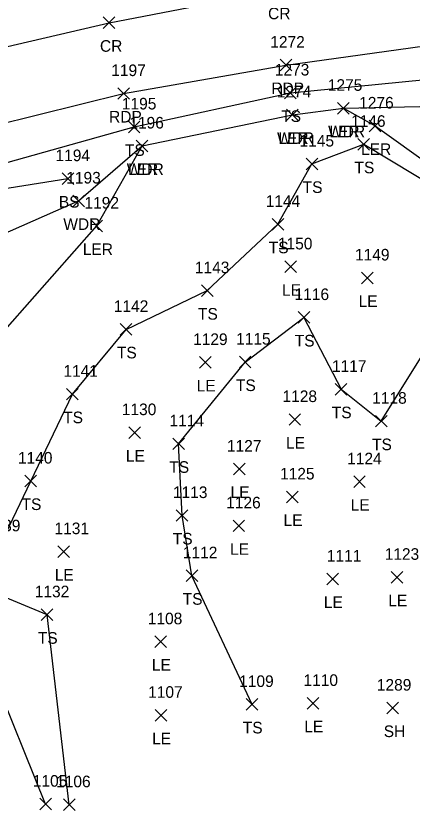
# Model space of a CAD drawing. Extents: x 1586965 to 1590952, y 716317 to 720029.
# Drawn here: x 1587642.6 to 1587710.9, y 719699 to 719836.9 of the extents above; entities that cross this region are included whole.
import ezdxf

# ---------------------------------------------------------------- set-up
doc = ezdxf.new("R2010")
doc.units = 0
for name, color, linetype in [('L_A', 7, 'Continuous'), ('L_I', 7, 'Continuous'), ('L_TIC', 7, 'Continuous'), ('LARO', 7, 'Continuous'), ('LAWA', 7, 'Continuous'), ('LELB', 7, 'Continuous'), ('P_A', 7, 'Continuous'), ('P_I', 7, 'Continuous'), ('P_TIC', 7, 'Continuous'), ('PET', 7, 'Continuous'), ('PRC', 7, 'Continuous')]:
    doc.layers.add(name, color=color, linetype=linetype)

msp = doc.modelspace()

# ---------------------------------------------------------------- linework, layer by layer
at = {"layer": 'L_TIC'}
for points in [[(1587688.98, 719822.61), (1587690.98, 719824.61)], [(1587690.98, 719822.61), (1587688.98, 719824.61)], [(1587689.31, 719818.83), (1587691.31, 719820.83)], [(1587691.31, 719818.83), (1587689.31, 719820.83)], [(1587689.31, 719818.83), (1587691.31, 719820.83)], [(1587691.31, 719818.83), (1587689.31, 719820.83)], [(1587698.11, 719819.97), (1587700.11, 719821.97)], [(1587700.11, 719819.97), (1587698.11, 719821.97)], [(1587698.11, 719819.97), (1587700.11, 719821.97)], [(1587700.11, 719819.97), (1587698.11, 719821.97)], [(1587662.03, 719816.76), (1587664.03, 719818.76)], [(1587664.03, 719816.76), (1587662.03, 719818.76)], [(1587703.58, 719816.92), (1587705.58, 719818.92)], [(1587705.58, 719816.92), (1587703.58, 719818.92)], [(1587663.38, 719813.47), (1587665.38, 719815.47)], [(1587665.38, 719813.47), (1587663.38, 719815.47)], [(1587663.38, 719813.47), (1587665.38, 719815.47)], [(1587665.38, 719813.47), (1587663.38, 719815.47)], [(1587701.61, 719813.76), (1587703.61, 719815.76)], [(1587703.61, 719813.76), (1587701.61, 719815.76)], [(1587692.68, 719810.37), (1587694.68, 719812.37)], [(1587694.68, 719810.37), (1587692.68, 719812.37)], [(1587650.6, 719807.85), (1587652.6, 719809.85)], [(1587652.6, 719807.85), (1587650.6, 719809.85)], [(1587652.44, 719804), (1587654.44, 719806)], [(1587654.44, 719804), (1587652.44, 719806)], [(1587655.59, 719799.68), (1587657.59, 719801.68)], [(1587657.59, 719799.68), (1587655.59, 719801.68)], [(1587686.83, 719799.98), (1587688.83, 719801.98)], [(1587688.83, 719799.98), (1587686.83, 719801.98)], [(1587689.03, 719792.65), (1587691.03, 719794.65)], [(1587691.03, 719792.65), (1587689.03, 719794.65)], [(1587702.24, 719790.74), (1587704.24, 719792.74)], [(1587704.24, 719790.74), (1587702.24, 719792.74)], [(1587674.63, 719788.54), (1587676.63, 719790.54)], [(1587676.63, 719788.54), (1587674.63, 719790.54)], [(1587691.31, 719783.92), (1587693.31, 719785.92)], [(1587693.31, 719783.92), (1587691.31, 719785.92)], [(1587660.64, 719781.87), (1587662.64, 719783.87)], [(1587662.64, 719781.87), (1587660.64, 719783.87)], [(1587674.32, 719776.17), (1587676.32, 719778.17)], [(1587676.32, 719776.17), (1587674.32, 719778.17)], [(1587681.17, 719776.24), (1587683.17, 719778.24)], [(1587683.17, 719776.24), (1587681.17, 719778.24)], [(1587651.38, 719770.7), (1587653.38, 719772.7)], [(1587653.38, 719770.7), (1587651.38, 719772.7)], [(1587697.7, 719771.55), (1587699.7, 719773.55)], [(1587699.7, 719771.55), (1587697.7, 719773.55)], [(1587689.74, 719766.34), (1587691.74, 719768.34)], [(1587691.74, 719766.34), (1587689.74, 719768.34)], [(1587704.64, 719766.05), (1587706.64, 719768.05)], [(1587706.64, 719766.05), (1587704.64, 719768.05)], [(1587662.11, 719764.09), (1587664.11, 719766.09)], [(1587664.11, 719764.09), (1587662.11, 719766.09)], [(1587669.68, 719762.15), (1587671.68, 719764.15)], [(1587671.68, 719762.15), (1587669.68, 719764.15)], [(1587680.16, 719757.8), (1587682.16, 719759.8)], [(1587682.16, 719757.8), (1587680.16, 719759.8)], [(1587644.2, 719755.74), (1587646.2, 719757.74)], [(1587646.2, 719755.74), (1587644.2, 719757.74)], [(1587700.88, 719755.61), (1587702.88, 719757.61)], [(1587702.88, 719755.61), (1587700.88, 719757.61)], [(1587689.3, 719753), (1587691.3, 719755)], [(1587691.3, 719753), (1587689.3, 719755)], [(1587670.28, 719749.8), (1587672.28, 719751.8)], [(1587672.28, 719749.8), (1587670.28, 719751.8)], [(1587680.08, 719748.02), (1587682.08, 719750.02)], [(1587682.08, 719748.02), (1587680.08, 719750.02)], [(1587649.85, 719743.58), (1587651.85, 719745.58)], [(1587651.85, 719743.58), (1587649.85, 719745.58)], [(1587671.99, 719739.42), (1587673.99, 719741.42)], [(1587673.99, 719739.42), (1587671.99, 719741.42)], [(1587696.26, 719738.87), (1587698.26, 719740.87)], [(1587698.26, 719738.87), (1587696.26, 719740.87)], [(1587707.35, 719739.16), (1587709.35, 719741.16)], [(1587709.35, 719739.16), (1587707.35, 719741.16)], [(1587647.01, 719732.7), (1587649.01, 719734.7)], [(1587649.01, 719732.7), (1587647.01, 719734.7)], [(1587666.59, 719728.05), (1587668.59, 719730.05)], [(1587668.59, 719728.05), (1587666.59, 719730.05)], [(1587682.35, 719717.25), (1587684.35, 719719.25)], [(1587684.35, 719717.25), (1587682.35, 719719.25)], [(1587692.88, 719717.43), (1587694.88, 719719.43)], [(1587694.88, 719717.43), (1587692.88, 719719.43)], [(1587666.64, 719715.38), (1587668.64, 719717.38)], [(1587668.64, 719715.38), (1587666.64, 719717.38)], [(1587706.59, 719716.62), (1587708.59, 719718.62)], [(1587708.59, 719716.62), (1587706.59, 719718.62)], [(1587646.76, 719700.07), (1587648.76, 719702.07)], [(1587648.76, 719700.07), (1587646.76, 719702.07)], [(1587650.83, 719699.97), (1587652.83, 719701.97)], [(1587652.83, 719699.97), (1587650.83, 719701.97)]]:
    msp.add_lwpolyline(points, dxfattribs=at)
at = {"layer": 'LARO'}
for points in [[(1587633.4, 719774.52), (1587656.59, 719800.68), (1587664.38, 719814.47), (1587690.31, 719819.83), (1587699.11, 719820.97), (1587704.58, 719817.92), (1587714.5, 719810.87)], [(1587647.76, 719701.07), (1587638.4, 719724.05)]]:
    msp.add_lwpolyline(points, dxfattribs=at)
at = {"layer": 'LAWA'}
msp.add_lwpolyline([(1587401.27, 719626.51), (1587435.01, 719634.6), (1587448.14, 719647.08), (1587470.91, 719665.01), (1587461.04, 719696.06), (1587450.54, 719719.33), (1587487.07, 719738.78), (1587518.72, 719752.12), (1587550.39, 719765.58), (1587600.64, 719780.12), (1587625.51, 719792.71), (1587653.44, 719805), (1587664.38, 719814.47), (1587690.31, 719819.83), (1587699.11, 719820.97), (1587725.45, 719821.57), (1587738.15, 719822.66), (1587747.89, 719823.3), (1587771.26, 719823.5), (1587792.66, 719819.32), (1587813.67, 719812.11)], dxfattribs=at)
at = {"layer": 'LELB'}
for points in [[(1587398.24, 719722.21), (1587438.94, 719742.74), (1587477.78, 719760.7), (1587507.65, 719771.73), (1587544.05, 719780.86), (1587591.35, 719799.64), (1587619.1, 719805.45), (1587663.03, 719817.76), (1587689.98, 719823.61), (1587724.39, 719827.01), (1587769.54, 719828.25), (1587817.81, 719818.92)], [(1587398.24, 719722.21), (1587438.94, 719742.74), (1587477.78, 719760.7), (1587507.65, 719771.73), (1587544.05, 719780.86), (1587591.35, 719799.64), (1587619.1, 719805.45), (1587663.03, 719817.76), (1587689.98, 719823.61), (1587724.39, 719827.01), (1587769.54, 719828.25), (1587817.81, 719818.92)], [(1587651.83, 719700.97), (1587648.01, 719733.7), (1587631.26, 719740.62), (1587615.07, 719741.57), (1587623.3, 719748.63), (1587638.24, 719757.75), (1587639.59, 719745.07), (1587645.2, 719756.74), (1587652.38, 719771.7), (1587661.64, 719782.87), (1587675.63, 719789.54), (1587687.83, 719800.98), (1587693.68, 719811.37), (1587702.61, 719814.76), (1587716.08, 719806.7), (1587717.74, 719791.78), (1587733.84, 719775.17), (1587724.64, 719762.06), (1587727.41, 719748.69)], [(1587651.83, 719700.97), (1587648.01, 719733.7), (1587631.26, 719740.62), (1587615.07, 719741.57), (1587623.3, 719748.63), (1587638.24, 719757.75), (1587639.59, 719745.07), (1587645.2, 719756.74), (1587652.38, 719771.7), (1587661.64, 719782.87), (1587675.63, 719789.54), (1587687.83, 719800.98), (1587693.68, 719811.37), (1587702.61, 719814.76), (1587716.08, 719806.7), (1587717.74, 719791.78), (1587733.84, 719775.17), (1587724.64, 719762.06), (1587727.41, 719748.69)], [(1587400.93, 719718.94), (1587441.36, 719738.52), (1587479.32, 719758.06), (1587509.44, 719768.45), (1587545.37, 719776.35), (1587593.67, 719793.11), (1587606.58, 719796.72), (1587619.17, 719803.04), (1587621.11, 719802.76), (1587621.24, 719800.99), (1587625.17, 719804.67), (1587651.6, 719808.85)], [(1587400.93, 719718.94), (1587441.36, 719738.52), (1587479.32, 719758.06), (1587509.44, 719768.45), (1587545.37, 719776.35), (1587593.67, 719793.11), (1587606.58, 719796.72), (1587619.17, 719803.04), (1587621.11, 719802.76), (1587621.24, 719800.99), (1587625.17, 719804.67), (1587651.6, 719808.85)], [(1587683.35, 719718.25), (1587672.99, 719740.42), (1587671.28, 719750.8), (1587670.68, 719763.15), (1587682.17, 719777.24), (1587692.31, 719784.92), (1587698.7, 719772.55), (1587705.64, 719767.05), (1587712.7, 719778.35), (1587717.65, 719760.19), (1587724.02, 719737.47), (1587722.82, 719731.15), (1587722.81, 719720.17)], [(1587683.35, 719718.25), (1587672.99, 719740.42), (1587671.28, 719750.8), (1587670.68, 719763.15), (1587682.17, 719777.24), (1587692.31, 719784.92), (1587698.7, 719772.55), (1587705.64, 719767.05), (1587712.7, 719778.35), (1587717.65, 719760.19), (1587724.02, 719737.47), (1587722.82, 719731.15), (1587722.81, 719720.17)]]:
    msp.add_lwpolyline(points, dxfattribs=at)
at = {"layer": 'P_TIC'}
for points in [[(1587657.7, 719834.7), (1587659.7, 719836.7)], [(1587659.7, 719834.7), (1587657.7, 719836.7)], [(1587688.19, 719827.4), (1587690.19, 719829.4)], [(1587690.19, 719827.4), (1587688.19, 719829.4)], [(1587660.21, 719822.51), (1587662.21, 719824.51)], [(1587662.21, 719822.51), (1587660.21, 719824.51)]]:
    msp.add_lwpolyline(points, dxfattribs=at)
at = {"layer": 'PET'}
msp.add_lwpolyline([(1587395.82, 719726.18), (1587435.88, 719747.89), (1587475.69, 719765.52), (1587505.58, 719777), (1587541.23, 719789.76), (1587588.97, 719805.25), (1587616.65, 719812.47), (1587661.21, 719823.51), (1587689.19, 719828.4), (1587723.88, 719833.21), (1587769.59, 719834.05), (1587819.16, 719826.14)], dxfattribs=at)
at = {"layer": 'PRC'}
msp.add_lwpolyline([(1587388.91, 719738.13), (1587428.57, 719759.37), (1587470.76, 719777.76), (1587498.92, 719788.92), (1587537.38, 719802.71), (1587585.33, 719817.72), (1587613.69, 719825.22), (1587658.7, 719835.7), (1587687.69, 719841.3), (1587721.6, 719845.66), (1587770.57, 719846.88), (1587822.37, 719838.71)], dxfattribs=at)
msp.add_lwpolyline([(1587388.91, 719738.13), (1587428.57, 719759.37), (1587470.76, 719777.76), (1587498.92, 719788.92), (1587537.38, 719802.71), (1587585.33, 719817.72), (1587613.69, 719825.22), (1587658.7, 719835.7), (1587687.69, 719841.3), (1587721.6, 719845.66), (1587770.57, 719846.88), (1587822.37, 719838.71)], dxfattribs=at)

# ---------------------------------------------------------------- texts
at = {"layer": 'L_A'}
for s, p in [('TS', (1587688.39, 719818.61)), ('WDR', (1587687.67, 719814.83)), ('LER', (1587687.89, 719814.83)), ('WDR', (1587696.47, 719815.97)), ('LER', (1587696.69, 719815.97)), ('TS', (1587661.44, 719812.76)), ('LER', (1587702.16, 719812.92)), ('WDR', (1587661.75, 719809.47)), ('LER', (1587661.97, 719809.47)), ('TS', (1587701.02, 719809.76)), ('TS', (1587692.09, 719806.37)), ('BS', (1587650.04, 719803.85)), ('WDR', (1587650.81, 719800)), ('LER', (1587654.17, 719795.68)), ('TS', (1587686.24, 719795.98)), ('LE', (1587688.52, 719788.65)), ('LE', (1587701.73, 719786.74)), ('TS', (1587674.04, 719784.54)), ('TS', (1587690.72, 719779.92)), ('TS', (1587660.05, 719777.87)), ('LE', (1587673.81, 719772.17)), ('TS', (1587680.58, 719772.24)), ('TS', (1587650.79, 719766.7)), ('TS', (1587697.11, 719767.55)), ('LE', (1587689.22, 719762.34)), ('TS', (1587704.05, 719762.05)), ('LE', (1587661.6, 719760.09)), ('TS', (1587669.09, 719758.15)), ('LE', (1587679.65, 719753.8)), ('TS', (1587643.61, 719751.74)), ('LE', (1587700.37, 719751.61)), ('LE', (1587688.79, 719749)), ('TS', (1587669.69, 719745.8)), ('LE', (1587679.57, 719744.02)), ('LE', (1587649.34, 719739.58)), ('TS', (1587671.4, 719735.42)), ('LE', (1587695.74, 719734.87)), ('LE', (1587706.84, 719735.16)), ('TS', (1587646.42, 719728.7)), ('LE', (1587666.08, 719724.05)), ('TS', (1587681.76, 719713.25)), ('LE', (1587692.36, 719713.43)), ('SH', (1587706.07, 719712.62)), ('LE', (1587666.13, 719711.38))]:
    msp.add_text(s, height=2, dxfattribs=at).set_placement(p)
at = {"layer": 'L_I'}
for s, p in [('1273', (1587687.28, 719826.61)), ('1275', (1587696.42, 719823.97)), ('1275', (1587696.42, 719823.97)), ('1274', (1587687.61, 719822.83)), ('1274', (1587687.61, 719822.83)), ('1195', (1587660.91, 719820.76)), ('1276', (1587701.83, 719820.92)), ('1196', (1587662.2, 719817.47)), ('1196', (1587662.2, 719817.47)), ('1146', (1587700.43, 719817.76)), ('1145', (1587691.55, 719814.37)), ('1194', (1587649.47, 719811.85)), ('1193', (1587651.32, 719808)), ('1192', (1587654.46, 719803.68)), ('1144', (1587685.71, 719803.98)), ('1150', (1587687.82, 719796.65)), ('1149', (1587701.11, 719794.74)), ('1143', (1587673.5, 719792.54)), ('1116', (1587690.69, 719787.92)), ('1142', (1587659.52, 719785.87)), ('1129', (1587673.19, 719780.17)), ('1115', (1587680.61, 719780.24)), ('1141', (1587650.82, 719774.7)), ('1117', (1587697.14, 719775.55)), ('1128', (1587688.61, 719770.34)), ('1118', (1587704.08, 719770.05)), ('1130', (1587660.9, 719768.09)), ('1114', (1587669.12, 719766.15)), ('1127', (1587679.03, 719761.8)), ('1140', (1587642.99, 719759.74)), ('1124', (1587699.76, 719759.61)), ('1125', (1587688.18, 719757)), ('1113', (1587669.72, 719753.8)), ('1126', (1587678.9, 719752.02)), ('1139', (1587637.46, 719748.07)), ('1131', (1587649.29, 719747.58)), ('1112', (1587671.43, 719743.42)), ('1123', (1587706.23, 719743.16)), ('1111', (1587696.26, 719742.87)), ('1132', (1587645.89, 719736.7)), ('1108', (1587665.38, 719732.05)), ('1109', (1587681.14, 719721.25)), ('1110', (1587692.23, 719721.43)), ('1289', (1587704.88, 719720.62)), ('1107', (1587665.44, 719719.38)), ('1105', (1587645.55, 719704.07)), ('1106', (1587649.57, 719703.97))]:
    msp.add_text(s, height=2, dxfattribs=at).set_placement(p)
at = {"layer": 'P_A'}
for s, p in [('CR', (1587686.12, 719836.3)), ('CR', (1587657.13, 719830.7)), ('RDP', (1587686.68, 719823.4)), ('RDP', (1587658.7, 719818.51))]:
    msp.add_text(s, height=2, dxfattribs=at).set_placement(p)
at = {"layer": 'P_I'}
for s, p in [('1272', (1587686.5, 719831.4)), ('1197', (1587659.08, 719826.51))]:
    msp.add_text(s, height=2, dxfattribs=at).set_placement(p)

doc.saveas('drawing.dxf')
